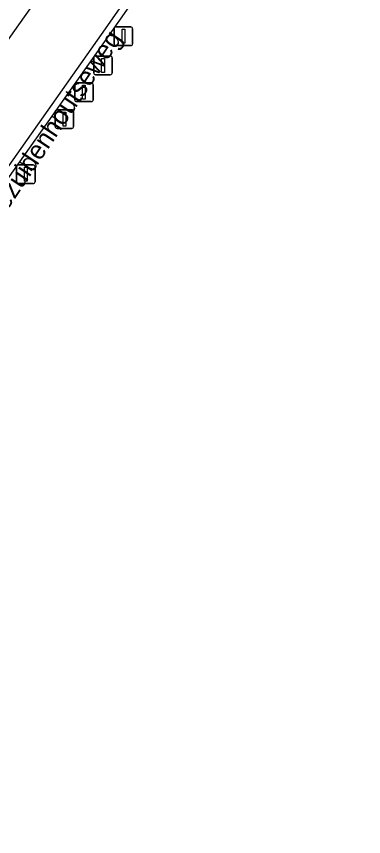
# Model space of a CAD drawing. Extents: x 157154 to 159278, y 385000 to 386650.
# Drawn here: x 159160.66 to 159179.26, y 385081.17 to 385125.13 of the extents above; entities that cross this region are included whole.
import ezdxf

# ---------------------------------------------------------------- set-up
doc = ezdxf.new("R2010")
doc.units = 0
for name, color, linetype in [('IMGEO_Afsluitpaal', 7, 'Continuous'), ('IMGEO_Openbare_ruimte_label', 7, 'Continuous'), ('IMGEO_Rijbaan_lokaal_gesloten', 7, 'Continuous'), ('IMGEO_Rijbaan_lokaal_halfverhard', 7, 'Continuous'), ('IMGEO_Voetpad_open', 7, 'Continuous')]:
    doc.layers.add(name, color=color, linetype=linetype)

msp = doc.modelspace()

# ---------------------------------------------------------------- linework, layer by layer
at = {"layer": 'IMGEO_Afsluitpaal'}
for p, q in [((159165.894, 385123.667), (159165.894, 385124.467)), ((159165.894, 385124.467), (159165.894, 385123.667)), ((159165.994, 385124.567), (159166.784, 385124.567)), ((159166.784, 385124.567), (159165.994, 385124.567)), ((159166.884, 385124.467), (159166.884, 385123.667)), ((159166.884, 385123.667), (159166.884, 385124.467)), ((159166.784, 385123.567), (159165.994, 385123.567)), ((159165.994, 385123.567), (159166.784, 385123.567)), ((159164.898, 385123.006), (159165.688, 385123.006)), ((159165.688, 385123.006), (159164.898, 385123.006)), ((159164.798, 385122.106), (159164.798, 385122.906)), ((159164.798, 385122.906), (159164.798, 385122.106)), ((159165.788, 385122.906), (159165.788, 385122.106)), ((159165.788, 385122.106), (159165.788, 385122.906)), ((159165.688, 385122.006), (159164.898, 385122.006)), ((159164.898, 385122.006), (159165.688, 385122.006)), ((159163.779, 385120.669), (159163.779, 385121.469)), ((159163.779, 385121.469), (159163.779, 385120.669)), ((159163.879, 385121.569), (159164.669, 385121.569)), ((159164.669, 385121.569), (159163.879, 385121.569)), ((159164.769, 385121.469), (159164.769, 385120.669)), ((159164.769, 385120.669), (159164.769, 385121.469)), ((159164.669, 385120.569), (159163.879, 385120.569)), ((159163.879, 385120.569), (159164.669, 385120.569)), ((159162.733, 385119.227), (159162.733, 385120.027)), ((159162.733, 385120.027), (159162.733, 385119.227)), ((159162.833, 385120.127), (159163.623, 385120.127)), ((159163.623, 385120.127), (159162.833, 385120.127)), ((159163.723, 385120.027), (159163.723, 385119.227)), ((159163.723, 385119.227), (159163.723, 385120.027)), ((159163.623, 385119.127), (159162.833, 385119.127)), ((159162.833, 385119.127), (159163.623, 385119.127)), ((159160.668, 385116.269), (159160.668, 385117.069)), ((159160.668, 385117.069), (159160.668, 385116.269)), ((159160.768, 385117.169), (159161.558, 385117.169)), ((159161.558, 385117.169), (159160.768, 385117.169)), ((159161.658, 385117.069), (159161.658, 385116.269)), ((159161.658, 385116.269), (159161.658, 385117.069)), ((159161.558, 385116.169), (159160.768, 385116.169)), ((159160.768, 385116.169), (159161.558, 385116.169))]:
    msp.add_line(p, q, dxfattribs=at)
for points in [[(159166.314, 385124.442), (159166.464, 385124.442), (159166.464, 385123.692), (159166.314, 385123.692), (159166.314, 385124.442)], [(159165.218, 385122.881), (159165.368, 385122.881), (159165.368, 385122.131), (159165.218, 385122.131), (159165.218, 385122.881)], [(159164.199, 385121.444), (159164.349, 385121.444), (159164.349, 385120.694), (159164.199, 385120.694), (159164.199, 385121.444)], [(159163.153, 385120.002), (159163.303, 385120.002), (159163.303, 385119.252), (159163.153, 385119.252), (159163.153, 385120.002)], [(159161.088, 385117.044), (159161.238, 385117.044), (159161.238, 385116.294), (159161.088, 385116.294), (159161.088, 385117.044)]]:
    msp.add_lwpolyline(points, dxfattribs=at)
for centre, start, end in [((159165.994, 385124.467), 90, 180), ((159165.994, 385124.467), 90, 180), ((159166.784, 385124.467), 0, 90), ((159166.784, 385124.467), 360, 90), ((159165.994, 385123.667), 180, 270), ((159165.994, 385123.667), 180, 270), ((159166.784, 385123.667), 270, 0), ((159166.784, 385123.667), 270, 0), ((159164.898, 385122.906), 90, 180), ((159164.898, 385122.906), 90, 180), ((159165.688, 385122.906), 0, 90), ((159165.688, 385122.906), 360, 90), ((159164.898, 385122.106), 180, 270), ((159164.898, 385122.106), 180, 270), ((159165.688, 385122.106), 270, 0), ((159165.688, 385122.106), 270, 0), ((159163.879, 385121.469), 90, 180), ((159163.879, 385121.469), 90, 180), ((159164.669, 385121.469), 0, 90), ((159164.669, 385121.469), 360, 90), ((159163.879, 385120.669), 180, 270), ((159163.879, 385120.669), 180, 270), ((159164.669, 385120.669), 270, 0), ((159164.669, 385120.669), 270, 0), ((159162.833, 385120.027), 90, 180), ((159162.833, 385120.027), 90, 180), ((159163.623, 385120.027), 0, 90), ((159163.623, 385120.027), 360, 90), ((159162.833, 385119.227), 180, 270), ((159162.833, 385119.227), 180, 270), ((159163.623, 385119.227), 270, 0), ((159163.623, 385119.227), 270, 0), ((159160.768, 385117.069), 90, 180), ((159160.768, 385117.069), 90, 180), ((159161.558, 385117.069), 0, 90), ((159161.558, 385117.069), 360, 90), ((159160.768, 385116.269), 180, 270), ((159160.768, 385116.269), 180, 270), ((159161.558, 385116.269), 270, 0), ((159161.558, 385116.269), 270, 0)]:
    msp.add_arc(centre, 0.1, start, end, dxfattribs=at)
at = {"layer": 'IMGEO_Rijbaan_lokaal_gesloten'}
for points in [[(159193.211, 385168.845), (159187.56, 385161.643), (159181.331, 385153.165), (159172.644, 385141.459), (159166.702, 385133.073), (159158.593, 385121.626), (159152.041, 385112.291), (159143.441, 385100.038), (159135.503, 385088.629), (159130.039, 385080.599), (159124.39, 385072.298), (159120.076, 385065.821), (159112.721, 385054.945), (159108.114, 385048.109), (159097.939, 385033.062), (159087.928, 385018.043), (159086.779, 385016.337), (159085.933, 385015.081), (159084.062, 385012.304), (159080.634, 385007.363), (159077.549, 385002.725)], [(159080.766, 385000.498), (159084.558, 385006.205), (159091.41, 385016.362), (159101.183, 385030.766), (159107.116, 385039.583), (159113.235, 385048.651), (159133.732, 385079.03), (159149.547, 385101.952), (159165.213, 385124.168), (159173.703, 385136.301), (159179.735, 385144.683), (159187.963, 385155.555)]]:
    msp.add_lwpolyline(points, dxfattribs=at)
at = {"layer": 'IMGEO_Rijbaan_lokaal_halfverhard'}
for points in [[(159183.989, 385149.748), (159180.021, 385144.473), (159173.992, 385136.096), (159165.503, 385123.964), (159162.556, 385119.784)], [(159162.556, 385119.784), (159160.83, 385117.337)], [(159160.83, 385117.337), (159149.838, 385101.749), (159145.304, 385095.179)]]:
    msp.add_lwpolyline(points, dxfattribs=at)
at = {"layer": 'IMGEO_Voetpad_open'}
for points in [[(159163.18, 385119.339), (159162.556, 385119.784)], [(159161.48, 385116.856), (159160.83, 385117.337)]]:
    msp.add_lwpolyline(points, dxfattribs=at)

# ---------------------------------------------------------------- texts
at = {"layer": 'IMGEO_Openbare_ruimte_label'}
msp.add_text('Bezuidenhoutseweg', height=1, rotation=56.2146, dxfattribs=at).set_placement((159159.65, 385113.948))

doc.saveas('drawing.dxf')
